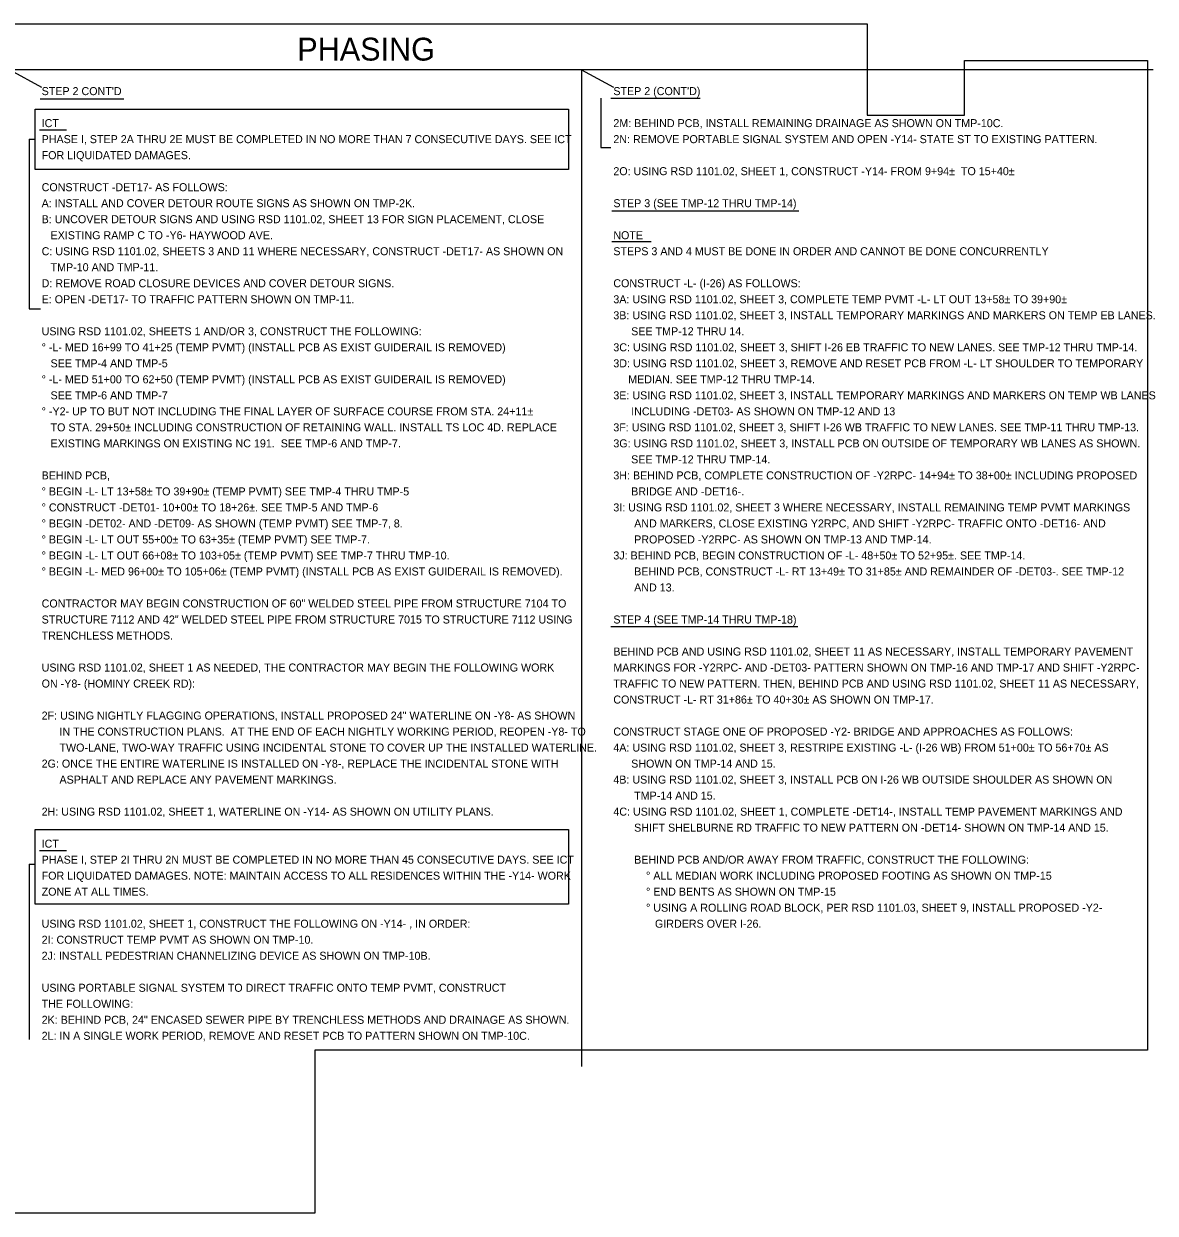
# Model space of a CAD drawing. Extents: x 2483905 to 2494512, y 366160 to 372330.
# Drawn here: x 2487524 to 2488513, y 370218 to 371258 of the extents above; entities that cross this region are included whole.
import ezdxf

# ---------------------------------------------------------------- set-up
doc = ezdxf.new("R2010")
doc.units = 0
for name, color, linetype in [('Scratch_Level_6', 7, 'Continuous'), ('TC SHEET BORDER LINE THIN', 7, 'Continuous'), ('TC SHEET LAYOUT SHAPE', 7, 'Continuous'), ('TC SHEET TEXT', 7, 'Continuous')]:
    doc.layers.add(name, color=color, linetype=linetype)

msp = doc.modelspace()

# ---------------------------------------------------------------- linework, layer by layer
at = {"layer": 'Scratch_Level_6'}
for p, q in [((2487511.6, 371218), (2487539.5, 371202.9)), ((2488011.6, 371218), (2488039.5, 371202.9))]:
    msp.add_line(p, q, dxfattribs=at)
at = {"layer": 'TC SHEET BORDER LINE THIN'}
for p, q in [((2488511.6, 371218), (2487011.6, 371218)), ((2488011.6, 371218), (2488011.6, 370346.5)), ((2487538.3, 371192.8), (2487611.5, 371192.8)), ((2488037.4, 371193.3), (2488115.4, 371193.3)), ((2487528.5, 371157.3), (2487533.9, 371157.3)), ((2487528.5, 371157.3), (2487528.5, 371009)), ((2487537.7, 371165.5), (2487561.3, 371165.5)), ((2488038.3, 371094.8), (2488201.7, 371094.8)), ((2488038.1, 371067.8), (2488072.5, 371067.8)), ((2487528.5, 371009), (2487538.6, 371009)), ((2488037.4, 370731.3), (2488200.8, 370731.3)), ((2487537.7, 370535.5), (2487561.3, 370535.5)), ((2487528.5, 370523.6), (2487533.9, 370523.6))]:
    msp.add_line(p, q, dxfattribs=at)
for points in [[(2488028.5, 371193.3), (2488028.5, 371150), (2488037.4, 371150)], [(2487528.5, 370523.6), (2487528.5, 370370.3)]]:
    msp.add_lwpolyline(points, dxfattribs=at)
for points in [[(2487533.9, 371183.7), (2488000.2, 371183.7), (2488000.2, 371130.8), (2487533.9, 371130.8)], [(2487533.9, 370553.7), (2488000.2, 370553.7), (2488000.2, 370488.6), (2487533.9, 370488.6)]]:
    msp.add_lwpolyline(points, close=True, dxfattribs=at)
at = {"layer": 'TC SHEET LAYOUT SHAPE'}
msp.add_lwpolyline([(2487016.6, 370666.8), (2487016.6, 370976.2), (2487016.6, 371248.3), (2487026.6, 371258.3), (2487469.6, 371258.3), (2487940.6, 371258.3), (2488261.6, 371258.3), (2488261.6, 371178.3), (2488346.6, 371178.3), (2488346.6, 371226.3), (2488506.6, 371226.3), (2488506.6, 370891.3), (2488506.6, 370612.1), (2488506.6, 370360.8), (2487778.4, 370360.8), (2487778.4, 370218.3), (2487608.9, 370218.3), (2487256.1, 370218.3), (2487016.6, 370218.3)], close=True, dxfattribs=at)

# ---------------------------------------------------------------- texts
at = {"layer": 'TC SHEET BORDER LINE THIN'}
for s, p in [("STEP 2 CONT'D", (2487539.5, 371195.9)), ("STEP 2 (CONT'D)", (2488039.5, 371195.9)), ('ICT', (2487539.5, 371167.9)), ('2M: BEHIND PCB, INSTALL REMAINING DRAINAGE AS SHOWN ON TMP-10C.', (2488039.5, 371167.9)), ('PHASE I, STEP 2A THRU 2E MUST BE COMPLETED IN NO MORE THAN 7 CONSECUTIVE DAYS. SEE ICT', (2487539.5, 371153.9)), ('2N: REMOVE PORTABLE SIGNAL SYSTEM AND OPEN -Y14- STATE ST TO EXISTING PATTERN.', (2488039.5, 371153.9)), ('FOR LIQUIDATED DAMAGES.', (2487539.5, 371139.9)), ('2O: USING RSD 1101.02, SHEET 1, CONSTRUCT -Y14- FROM 9+94±  TO 15+40±', (2488039.5, 371125.9)), ('CONSTRUCT -DET17- AS FOLLOWS:', (2487539.5, 371111.9)), ('A: INSTALL AND COVER DETOUR ROUTE SIGNS AS SHOWN ON TMP-2K.', (2487539.5, 371097.9)), ('STEP 3 (SEE TMP-12 THRU TMP-14)', (2488039.5, 371097.9)), ('B: UNCOVER DETOUR SIGNS AND USING RSD 1101.02, SHEET 13 FOR SIGN PLACEMENT, CLOSE', (2487539.5, 371083.9)), ('   EXISTING RAMP C TO -Y6- HAYWOOD AVE.', (2487539.5, 371069.9)), ('NOTE', (2488039.5, 371069.9)), ('C: USING RSD 1101.02, SHEETS 3 AND 11 WHERE NECESSARY, CONSTRUCT -DET17- AS SHOWN ON', (2487539.5, 371055.9)), ('STEPS 3 AND 4 MUST BE DONE IN ORDER AND CANNOT BE DONE CONCURRENTLY', (2488039.5, 371055.9)), ('   TMP-10 AND TMP-11.', (2487539.5, 371041.9)), ('D: REMOVE ROAD CLOSURE DEVICES AND COVER DETOUR SIGNS.', (2487539.5, 371027.9)), ('CONSTRUCT -L- (I-26) AS FOLLOWS:', (2488039.5, 371027.9)), ('E: OPEN -DET17- TO TRAFFIC PATTERN SHOWN ON TMP-11.', (2487539.5, 371013.9)), ('3A: USING RSD 1101.02, SHEET 3, COMPLETE TEMP PVMT -L- LT OUT 13+58± TO 39+90±', (2488039.5, 371013.9)), ('3B: USING RSD 1101.02, SHEET 3, INSTALL TEMPORARY MARKINGS AND MARKERS ON TEMP EB LANES.', (2488039.5, 370999.9)), ('USING RSD 1101.02, SHEETS 1 AND/OR 3, CONSTRUCT THE FOLLOWING:', (2487539.5, 370985.9)), ('      SEE TMP-12 THRU 14.', (2488039.5, 370985.9)), ('° -L- MED 16+99 TO 41+25 (TEMP PVMT) (INSTALL PCB AS EXIST GUIDERAIL IS REMOVED)', (2487539.5, 370971.9)), ('3C: USING RSD 1101.02, SHEET 3, SHIFT I-26 EB TRAFFIC TO NEW LANES. SEE TMP-12 THRU TMP-14.', (2488039.5, 370971.9)), ('   SEE TMP-4 AND TMP-5', (2487539.5, 370957.9)), ('3D: USING RSD 1101.02, SHEET 3, REMOVE AND RESET PCB FROM -L- LT SHOULDER TO TEMPORARY', (2488039.5, 370957.9)), ('° -L- MED 51+00 TO 62+50 (TEMP PVMT) (INSTALL PCB AS EXIST GUIDERAIL IS REMOVED)', (2487539.5, 370943.9)), ('     MEDIAN. SEE TMP-12 THRU TMP-14.', (2488039.5, 370943.9)), ('   SEE TMP-6 AND TMP-7', (2487539.5, 370929.9)), ('3E: USING RSD 1101.02, SHEET 3, INSTALL TEMPORARY MARKINGS AND MARKERS ON TEMP WB LANES', (2488039.5, 370929.9)), ('° -Y2- UP TO BUT NOT INCLUDING THE FINAL LAYER OF SURFACE COURSE FROM STA. 24+11±', (2487539.5, 370915.9)), ('      INCLUDING -DET03- AS SHOWN ON TMP-12 AND 13', (2488039.5, 370915.9)), ('   TO STA. 29+50± INCLUDING CONSTRUCTION OF RETAINING WALL. INSTALL TS LOC 4D. REPLACE', (2487539.5, 370901.9)), ('3F: USING RSD 1101.02, SHEET 3, SHIFT I-26 WB TRAFFIC TO NEW LANES. SEE TMP-11 THRU TMP-13.', (2488039.5, 370901.9)), ('   EXISTING MARKINGS ON EXISTING NC 191.  SEE TMP-6 AND TMP-7.', (2487539.5, 370887.9)), ('3G: USING RSD 1101.02, SHEET 3, INSTALL PCB ON OUTSIDE OF TEMPORARY WB LANES AS SHOWN. ', (2488039.5, 370887.9)), ('      SEE TMP-12 THRU TMP-14.', (2488039.5, 370873.9)), ('BEHIND PCB, ', (2487539.5, 370859.9)), ('3H: BEHIND PCB, COMPLETE CONSTRUCTION OF -Y2RPC- 14+94± TO 38+00± INCLUDING PROPOSED', (2488039.5, 370859.9)), ('° BEGIN -L- LT 13+58± TO 39+90± (TEMP PVMT) SEE TMP-4 THRU TMP-5', (2487539.5, 370845.9)), ('      BRIDGE AND -DET16-.', (2488039.5, 370845.9)), ('° CONSTRUCT -DET01- 10+00± TO 18+26±. SEE TMP-5 AND TMP-6', (2487539.5, 370831.9)), ('3I: USING RSD 1101.02, SHEET 3 WHERE NECESSARY, INSTALL REMAINING TEMP PVMT MARKINGS', (2488039.5, 370831.9)), ('° BEGIN -DET02- AND -DET09- AS SHOWN (TEMP PVMT) SEE TMP-7, 8.', (2487539.5, 370817.9)), ('       AND MARKERS, CLOSE EXISTING Y2RPC, AND SHIFT -Y2RPC- TRAFFIC ONTO -DET16- AND', (2488039.5, 370817.9)), ('° BEGIN -L- LT OUT 55+00± TO 63+35± (TEMP PVMT) SEE TMP-7.', (2487539.5, 370803.9)), ('       PROPOSED -Y2RPC- AS SHOWN ON TMP-13 AND TMP-14.', (2488039.5, 370803.9)), ('° BEGIN -L- LT OUT 66+08± TO 103+05± (TEMP PVMT) SEE TMP-7 THRU TMP-10.', (2487539.5, 370789.9)), ('3J: BEHIND PCB, BEGIN CONSTRUCTION OF -L- 48+50± TO 52+95±. SEE TMP-14.', (2488039.5, 370789.9)), ('° BEGIN -L- MED 96+00± TO 105+06± (TEMP PVMT) (INSTALL PCB AS EXIST GUIDERAIL IS REMOVED).', (2487539.5, 370775.9)), ('       BEHIND PCB, CONSTRUCT -L- RT 13+49± TO 31+85± AND REMAINDER OF -DET03-. SEE TMP-12', (2488039.5, 370775.9)), ('       AND 13.', (2488039.5, 370761.9)), ('CONTRACTOR MAY BEGIN CONSTRUCTION OF 60" WELDED STEEL PIPE FROM STRUCTURE 7104 TO', (2487539.5, 370747.9)), ('STRUCTURE 7112 AND 42" WELDED STEEL PIPE FROM STRUCTURE 7015 TO STRUCTURE 7112 USING', (2487539.5, 370733.9)), ('STEP 4 (SEE TMP-14 THRU TMP-18)', (2488039.5, 370733.9)), ('TRENCHLESS METHODS.', (2487539.5, 370719.9)), ('BEHIND PCB AND USING RSD 1101.02, SHEET 11 AS NECESSARY, INSTALL TEMPORARY PAVEMENT', (2488039.5, 370705.9)), ('USING RSD 1101.02, SHEET 1 AS NEEDED, THE CONTRACTOR MAY BEGIN THE FOLLOWING WORK', (2487539.5, 370691.9)), ('MARKINGS FOR -Y2RPC- AND -DET03- PATTERN SHOWN ON TMP-16 AND TMP-17 AND SHIFT -Y2RPC- ', (2488039.5, 370691.9)), ('ON -Y8- (HOMINY CREEK RD):', (2487539.5, 370677.9)), ('TRAFFIC TO NEW PATTERN. THEN, BEHIND PCB AND USING RSD 1101.02, SHEET 11 AS NECESSARY,', (2488039.5, 370677.9)), ('CONSTRUCT -L- RT 31+86± TO 40+30± AS SHOWN ON TMP-17.', (2488039.5, 370663.9)), ('2F: USING NIGHTLY FLAGGING OPERATIONS, INSTALL PROPOSED 24" WATERLINE ON -Y8- AS SHOWN', (2487539.5, 370649.9)), ('      IN THE CONSTRUCTION PLANS.  AT THE END OF EACH NIGHTLY WORKING PERIOD, REOPEN -Y8- TO', (2487539.5, 370635.9)), ('CONSTRUCT STAGE ONE OF PROPOSED -Y2- BRIDGE AND APPROACHES AS FOLLOWS:', (2488039.5, 370635.9)), ('      TWO-LANE, TWO-WAY TRAFFIC USING INCIDENTAL STONE TO COVER UP THE INSTALLED WATERLINE.', (2487539.5, 370621.9)), ('4A: USING RSD 1101.02, SHEET 3, RESTRIPE EXISTING -L- (I-26 WB) FROM 51+00± TO 56+70± AS', (2488039.5, 370621.9)), ('2G: ONCE THE ENTIRE WATERLINE IS INSTALLED ON -Y8-, REPLACE THE INCIDENTAL STONE WITH', (2487539.5, 370607.9)), ('      SHOWN ON TMP-14 AND 15.', (2488039.5, 370607.9)), ('      ASPHALT AND REPLACE ANY PAVEMENT MARKINGS.', (2487539.5, 370593.9)), ('4B: USING RSD 1101.02, SHEET 3, INSTALL PCB ON I-26 WB OUTSIDE SHOULDER AS SHOWN ON ', (2488039.5, 370593.9)), ('       TMP-14 AND 15.', (2488039.5, 370579.9)), ('2H: USING RSD 1101.02, SHEET 1, WATERLINE ON -Y14- AS SHOWN ON UTILITY PLANS.', (2487539.5, 370565.9)), ('4C: USING RSD 1101.02, SHEET 1, COMPLETE -DET14-, INSTALL TEMP PAVEMENT MARKINGS AND ', (2488039.5, 370565.9)), ('       SHIFT SHELBURNE RD TRAFFIC TO NEW PATTERN ON -DET14- SHOWN ON TMP-14 AND 15.', (2488039.5, 370551.9)), ('ICT', (2487539.5, 370537.9)), ('PHASE I, STEP 2I THRU 2N MUST BE COMPLETED IN NO MORE THAN 45 CONSECUTIVE DAYS. SEE ICT', (2487539.5, 370523.9)), ('       BEHIND PCB AND/OR AWAY FROM TRAFFIC, CONSTRUCT THE FOLLOWING:', (2488039.5, 370523.9)), ('FOR LIQUIDATED DAMAGES. NOTE: MAINTAIN ACCESS TO ALL RESIDENCES WITHIN THE -Y14- WORK ', (2487539.5, 370509.9)), ('           ° ALL MEDIAN WORK INCLUDING PROPOSED FOOTING AS SHOWN ON TMP-15', (2488039.5, 370509.9)), ('ZONE AT ALL TIMES.', (2487539.5, 370495.9)), ('           ° END BENTS AS SHOWN ON TMP-15', (2488039.5, 370495.9)), ('           ° USING A ROLLING ROAD BLOCK, PER RSD 1101.03, SHEET 9, INSTALL PROPOSED -Y2-', (2488039.5, 370481.9)), ('USING RSD 1101.02, SHEET 1, CONSTRUCT THE FOLLOWING ON -Y14- , IN ORDER:', (2487539.5, 370467.9)), ('              GIRDERS OVER I-26.', (2488039.5, 370467.9)), ('2I: CONSTRUCT TEMP PVMT AS SHOWN ON TMP-10.', (2487539.5, 370453.9)), ('2J: INSTALL PEDESTRIAN CHANNELIZING DEVICE AS SHOWN ON TMP-10B.', (2487539.5, 370439.9)), ('USING PORTABLE SIGNAL SYSTEM TO DIRECT TRAFFIC ONTO TEMP PVMT, CONSTRUCT', (2487539.5, 370411.9)), ('THE FOLLOWING:', (2487539.5, 370397.9)), ('2K: BEHIND PCB, 24" ENCASED SEWER PIPE BY TRENCHLESS METHODS AND DRAINAGE AS SHOWN.', (2487539.5, 370383.9)), ('2L: IN A SINGLE WORK PERIOD, REMOVE AND RESET PCB TO PATTERN SHOWN ON TMP-10C.', (2487539.5, 370369.9))]:
    msp.add_text(s, height=7, dxfattribs=at).set_placement(p)
at = {"layer": 'TC SHEET TEXT'}
msp.add_text('PHASING', height=20, rotation=359.9999, dxfattribs=at).set_placement((2487763.1, 371226.1))

doc.saveas('drawing.dxf')
